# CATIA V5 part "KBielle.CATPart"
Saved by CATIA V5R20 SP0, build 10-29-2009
Part number: K_Bielle
Bounding box of the stored display mesh (mm): x 20 to 24, y 11.28 to 98.016, z 197.254 to 685.403
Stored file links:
  C:\Users\thinkmotion1\Desktop\Khaled_IAO_Pack2\IAO_2010_1392_rragonneau\CATIA_1392_rragonneau\KBielle.CATPart
  D:\Documents\Scolaire\MM2\IAO\Squelette\Product1.CATProduct
  C:\Users\thinkmotion1\Desktop\Khaled_IAO_Pack2\IAO_2010_1392_rragonneau\CATIA_1392_rragonneau\KSquelette de base.CATPart
  C:\Users\thinkmotion1\Desktop\Khaled_IAO_Pack2\IAO_2010_1392_rragonneau\CATIA_1392_rragonneau\KSquelette coulisso.CATPart
  C:\Users\thinkmotion1\Desktop\Khaled_IAO_Pack2\IAO_2010_1392_rragonneau\CATIA_1392_rragonneau\KSquelette  bielle.CATPart
  C:\Users\thinkmotion1\Desktop\Khaled_IAO_Pack2\IAO_2010_1392_rragonneau\CATIA_1392_rragonneau\KSquelette bati.CATPart
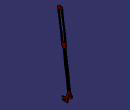
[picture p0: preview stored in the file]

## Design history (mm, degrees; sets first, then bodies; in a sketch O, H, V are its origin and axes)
Parameters
  diam_axe_bielle = 20 mm
  excentrique_griffe = 45 mm
  longueur_griffes = 20 mm
External parameters (linked from other documents)
  External.diametre_vilebrequin = 100 mm
Set1
  Sketch1 on Plane1, origin (0, 0, 0), H (0, 1, 0), V (0, 0, 1)
    line L1 (73.4087, 251.8961) -> (43.7125, 474.5265)
    point P2 (43.7125, 474.5265)
    point P3 (92.6235, 228.8572)
    line L2 (92.6235, 228.8572) -> (71.2242, 197.2539)
    point P4 (71.2242, 197.2539)
    line L3 (71.2242, 197.2539) -> (61.6659, 197.2539)
    point P5 (71.2242, 197.2539)
    line L4 (61.6659, 197.2539) -> (53.9096, 199.2539)
    line L5 (53.9096, 199.2539) -> (38.0161, 199.2539)
    line L6 (38.0161, 199.2539) -> (38.0161, 203.2539)
    line L7 (38.0161, 203.2539) -> (58.0161, 203.2539)
    line L8 (58.0161, 203.2539) -> (58.0161, 215.2539)
    line L9 (58.0161, 215.2539) -> (38.0161, 215.2539)
    line L10 (38.0161, 215.2539) -> (38.0161, 219.2539)
    line L11 (38.0161, 219.2539) -> (58.0161, 219.2539)
    point P14 (58.0161, 219.2539)
    point P15 (58.0161, 219.2539)
    point P16 (89.2682, 254.0116)
    point P17 (68.8944, 235.3193)
    line L12 (58.0161, 219.2539) -> (68.8944, 235.3193)
    line L13 (89.2682, 254.0116) -> (59.5721, 476.6419)
    point P18 (59.5721, 476.6419)
    arc A1 centre (26.9896, 660.4039) radius 25 from (51.7701, 663.7093) to (2.2091, 657.0985) ccw
    point P19 (26.9896, 660.4039)
    point P20 (51.7701, 663.7093)
    point P21 (2.2091, 657.0985)
    construction line L14 (8.0576, 657.8786) -> (47.8699, 663.1891)
    line L15 (2.2091, 657.0985) -> (22.0416, 508.4154)
    point P25 (83.0161, 240.3767)
    point P26 (71.6026, 515.0262)
    point P27 (51.7701, 663.7093)
    line L16 (51.7701, 663.7093) -> (71.6026, 515.0262)
    construction line L17 (26.9896, 660.4039) -> (46.8221, 511.7208)
    point P28 (46.8221, 511.7208)
    line L18 (34.9194, 661.4616) -> (54.7519, 512.7785)
    line L19 (38.8923, 510.663) -> (19.0598, 659.3462)
    arc A2 centre (46.8221, 511.7208) radius 8 from (54.7519, 512.7785) to (38.8923, 510.663) cw
    arc A3 centre (26.9896, 660.4039) radius 8 from (19.0598, 659.3462) to (34.9194, 661.4616) cw
    line L20 (22.0416, 508.4154) -> (43.7125, 474.5265)
    line L21 (59.5721, 476.6419) -> (71.6026, 515.0262)
    arc A4 centre (83.0161, 240.3767) radius 15 from (73.4087, 251.8961) to (68.8944, 235.3193) ccw
    point P33 (68.8944, 235.3193)
    arc A5 centre (83.0161, 240.3767) radius 15 from (92.6235, 228.8572) to (89.2682, 254.0116) ccw
    point P34 (92.6235, 228.8572)
    reference projected line E1 (79.6533, 265.5876) -> (37.2843, 583.2248) from Line2
    reference projected point E2 (83.0161, 240.3767) from DatumPoint1
    reference projected line E3 (43.8952, 533.6638) -> (30.6735, 632.7858) from Line3
    construction line L22 (73.4087, 251.8961) -> (89.2682, 254.0116)
    point P35 (89.2682, 254.0116)
    reference projected line E4 (79.6533, 265.5876) -> (37.2843, 583.2248) from Line2
    reference projected line E5 (79.6533, 265.5876) -> (37.2843, 583.2248) from Line2
    reference projected line E6 (79.6533, 265.5876) -> (37.2843, 583.2248) from Line2
    construction line L23 (20.6675, 508.2321) -> (59.2983, 513.3849)
    reference projected line E7 (79.6533, 265.5876) -> (37.2843, 583.2248) from Line2
    axis line L24 (47.3529, 475.0121) -> (57.1098, 476.3135)
    reference projected point E8 (36.9059, 586.0623) from Point3
    radius A1 = 25
    length L15 = 150 {= External.diametre_vilebrequin *1.5}
    length L3 = 9.5583
    length L6 = 4
    length L10 = 4
    distance L17 L18 = 8
    length L19 = 150 {= External.diametre_vilebrequin *1.5}
    radius A4 = 15
    radius A5 = 15
    length L8 = 12
    distance L3 L5 = 2
    angle L21 E6 = 155
    distance E8 L14 = 75 {= External.diametre_vilebrequin *3/4}
    distance L10 P25 = 45 {= excentrique_griffe}
    angle L5 L4 = 165.541
    distance L8 P25 = 25 {= excentrique_griffe -longueur_griffes}
    horizontal: L3 H, L5 H, L7 H, L9 H, L11 H
    vertical: L8 V, L10 V, L6 V
    coincidence: P14 L8, L2 P5, P19 L14, P21 L14, P20 L14, P4 P5, P20 P27, L1 L19, P17 P33, P34 L13, P3 P34, P25 E2, L17 E3, P35 P16, L23 P28, P26 L23, P18 L24, P2 L24, L6 L10, P14 P15
    parallelism: L13 L1, L12 L2, L1 E1, L15 L17, L13 L17, L24 L23, L15 L16
    tangency: A2 L18, A3 L18, A2 L19, A3 L19
    perpendicularity: L22 E4, L22 E5, L14 L17, L23 E7
Set2
  Plane1: linked copy from another document
  Point1: linked copy from another document
  Line1: linked copy from another document
  Line2: linked copy from another document
  DatumPoint1: linked copy from another document
  Line3: linked copy from another document
  Point2: linked copy from another document
  Point3: linked copy from another document
Body1 (main body)
  Pad1: profile Sketch1, direction (1, 0, 0), length 24, opposite side length -20
  Sketch2 on end face of Pad1, origin (24, 89.5322, 246.498), H (0, 1, 0), V (0, 0, 1)
    point P1 (-6.5161, -6.1213)
    reference projected arc E1 centre (-6.5161, -6.1213) radius 15 from (-16.8434, 4.7574) to (-18.6814, -14.8965) ccw from edge [face of Pad1 from Sketch1.A4 | end face of Pad1]
    concentricity: P1 E1
  Hole1: placed by Sketch2, at (24, 83.0161, 240.3767) direction (-1, 0, 0), diameter 10, through (limit type 3)
  Sketch3 on end face of Pad1, origin (24, 0, 0), H (0, 1, 0), V (0, 0, 1)
    line L1 (-36.4885, 696.3629) -> (9.078, 696.3629)
    line L2 (9.078, 696.3629) -> (43.5695, 437.7817)
    line L3 (43.5695, 437.7817) -> (-36.4885, 437.7817)
    line L4 (-36.4885, 437.7817) -> (-36.4885, 696.3629)
    reference projected line E1 (2.2091, 657.0985) -> (22.0416, 508.4154) from edge [start face of Pad1 | face of Pad1 from Sketch1.L15]
    reference projected line E2 (19.0598, 659.3462) -> (38.8923, 510.663) from edge [face of Pad1 from Sketch1.L19 | start face of Pad1]
    line L5 (34.8497, 699.8005) -> (69.3413, 441.2193)
    reference projected line E3 (54.7519, 512.7785) -> (34.9194, 661.4616) from edge [end face of Pad1 | face of Pad1 from Sketch1.L18]
    line L6 (34.8497, 699.8005) -> (60, 699.8005)
    line L7 (60, 699.8005) -> (100, 445.3088)
    line L8 (100, 445.3088) -> (69.3413, 441.2193)
    distance L2 E2 = 5
    distance E3 L5 = 5
    horizontal: L1 H, L3 H, L6 H
    vertical: L4 V
    parallelism: L2 E1, L5 L2
  Pocket1: profile Sketch3, direction (-1, 0, 0), through (limit type 3)
  Sketch4 on end face of Pad1, origin (24, 0, 0), H (0, 1, 0), V (0, 0, 1)
    line L1 (70.0696, 195.8844) -> (76.2911, 229.6605)
    point P1 (70.0696, 195.8844)
    point P2 (76.2911, 229.6605)
    line L2 (76.2911, 229.6605) -> (102.9487, 229.6605)
    point P3 (76.2911, 229.6605)
    point P4 (102.9487, 229.6605)
    line L3 (102.9487, 229.6605) -> (82.8063, 195.3795)
    point P5 (102.9487, 229.6605)
    line L4 (82.8063, 195.3795) -> (70.0696, 195.8844)
    point P7 (70.0696, 195.8844)
    coincidence: P3 L1, P5 L2, L4 P1, P4 P5, P3 P2, P7 P1
    horizontal: L2 H
  Pocket2: profile Sketch4, direction (-1, 0, 0), through (limit type 3)
  Fillet1: radius 5, on edge [face of Pocket2 from Sketch4.L1 | face of Pocket2 from Sketch4.L2]
  Sketch5 on end face of Pad1, origin (24, 0, 0), H (0, 1, 0), V (0, 0, 1)
    line L1 (48.6686, 475.1876) -> (77.0426, 262.4694)
    point P1 (48.6686, 475.1876)
    point P2 (77.0426, 262.4694)
    line L2 (54.616, 475.9809) -> (49.0252, 475.2351)
    reference projected line E1 (45.1302, 463.8981) -> (73.4087, 251.8961) from edge [start face of Pad1 | face of Pad1 from Sketch1.L1]
    reference projected line E2 (45.1302, 463.8981) -> (73.4087, 251.8961) from edge [start face of Pad1 | face of Pad1 from Sketch1.L1]
    reference projected line E3 (45.1302, 463.8981) -> (73.4087, 251.8961) from edge [start face of Pad1 | face of Pad1 from Sketch1.L1]
    reference projected point E4 (43.7125, 474.5265) from vertex [face of Pad1 from Sketch1.L1 | start face of Pad1 | face of Pad1 from Sketch1.L20]
    line L3 (54.616, 475.9809) -> (82.99, 263.2627)
    point P5 (82.99, 263.2627)
    line L4 (77.0426, 262.4694) -> (82.99, 263.2627)
    point P6 (77.0426, 262.4694)
    point P7 (82.99, 263.2627)
    reference projected line E5 (89.2682, 254.0116) -> (59.5721, 476.6419) from edge [start face of Pad1 | face of Pad1 from Sketch1.L13]
    reference projected line E6 (89.2682, 254.0116) -> (59.5721, 476.6419) from edge [start face of Pad1 | face of Pad1 from Sketch1.L13]
    reference projected point E7 (73.4087, 251.8961) from vertex [face of Pad1 from Sketch1.L1 | start face of Pad1 | face of Pad1 from Sketch1.A4]
    distance E3 L1 = 5
    distance L2 E4 = 0
    distance L3 E6 = 5
    distance L4 E7 = 10
    coincidence: L2 P1, P2 P6, P7 P5
    perpendicularity: L2 E1, L4 L3
    parallelism: L1 E2, L3 E5
  Pocket3: profile Sketch5, direction (-1, 0, 0), through (limit type 3)
  Chamfer1: length 5, angle 45, on edge [face of Pad1 from Sketch1.L11 | face of Pad1 from Sketch1.L12]
  Chamfer2: length 5, angle 45, on edge [face of Pad1 from Sketch1.L7 | face of Pad1 from Sketch1.L8]
  Fillet2: radius 2, on edge [face of Chamfer1 | face of Pad1 from Sketch1.L11]
  Fillet3: radius 2, on edge [face of Chamfer2 | face of Pad1 from Sketch1.L7]
  Fillet4: radius 2, on edge [face of Pad1 from Sketch1.L4 | face of Pad1 from Sketch1.L5]
Relations
  Hole1.Depth = diam_axe_bielle (deactivated)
